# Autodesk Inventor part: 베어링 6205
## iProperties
IsCustomPart: 1
Company: 한국ATC센터
Created: 2014-10
Part Number: 베어링 6205
Material: 강, 연강
Description: 깊은 그루브 볼 베어링
Document SubType Name: Modeling
Standard: KS B 2023
Designer: 한국ATC센터
Standards Organization: KS
Language: ko-KR
Size Designation: 6205 - 25 x 52 x 15
Categories: <MemberInstance><Categories><Category DisplayName="샤프트 부품" InternalName="7f7aeb1f-a693-4053-b835-cee3144e0d98" Mnemonic="SHFT"><Category DisplayName="베어링" Inter
Density: 7.86 g/cm^3
Mass: 129.543 g
Surface Area: 107.326 cm^2
Volume: 16.4813 cm^3
Author: KYOUNG IL JANG
Revision Number: 1
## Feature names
1. IDS_ARRAYBALL[SIMPL:T] [Circular Pattern]
